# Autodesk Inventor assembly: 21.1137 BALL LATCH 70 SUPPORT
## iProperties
Created: 2007-03
Part Number: 21.1137 BALL LATCH 70 SUPPORT
Document SubType Name: Assembly
Designer: Andy Moles
Author: Andy Moles
